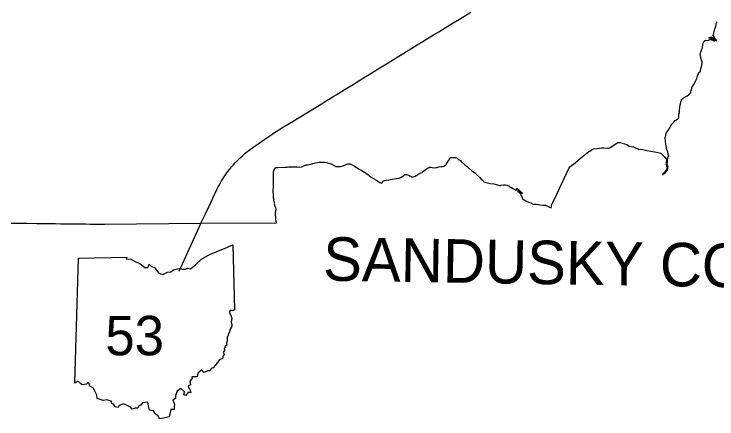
# Model space of a CAD drawing. Extents: x -82 to 873, y 0 to 440.
# Drawn here: x 319.9 to 400.6, y 101.2 to 147.6 of the extents above; entities that cross this region are included whole.
import ezdxf

# ---------------------------------------------------------------- set-up
doc = ezdxf.new("R2010")
doc.units = 0
for name, color, linetype in [('GM_X_Adjacent_County_Text', 7, 'Continuous'), ('GM_X_County', 7, 'Continuous'), ('GM_X_Interstate_Route', 7, 'Continuous'), ('PV_P_Text', 7, 'Continuous')]:
    doc.layers.add(name, color=color, linetype=linetype)

msp = doc.modelspace()

# ---------------------------------------------------------------- linework, layer by layer
at = {"layer": 'GM_X_County'}
msp.add_lwpolyline([(319.599, 123.64), (320.437, 123.634), (321.376, 123.619), (322.523, 123.608), (323.305, 123.602), (323.714, 123.595), (324.701, 123.586), (325.272, 123.578), (326.013, 123.57), (327.45, 123.55), (328.147, 123.544), (328.679, 123.539), (329.256, 123.531), (330.075, 123.525), (330.196, 123.525), (330.311, 123.522), (341.359, 123.643), (350.048, 123.686), (349.981, 124.068), (349.976, 124.298), (349.915, 124.639), (349.928, 124.886), (349.973, 125.03), (349.989, 125.249), (349.953, 125.379), (349.901, 125.562), (349.865, 125.676), (349.84, 125.756), (349.809, 125.765), (349.801, 125.795), (349.828, 125.859), (349.84, 125.945), (349.812, 126.003), (349.767, 126.059), (349.784, 126.084), (349.756, 126.278), (349.748, 126.339), (349.759, 126.377), (349.72, 126.413), (349.695, 126.483), (349.698, 126.621), (349.69, 126.818), (349.665, 127.403), (349.692, 127.863), (349.706, 128.237), (349.701, 128.775), (349.701, 129.121), (349.717, 129.515), (349.845, 129.942), (349.972, 130.025), (350.219, 130.045), (350.995, 130.081), (351.264, 130.078), (351.425, 130.106), (351.558, 130.097), (351.635, 130.075), (351.677, 130.086), (351.807, 130.086), (352.123, 130.1), (352.399, 130.09), (352.636, 130.084), (352.88, 130.106), (352.963, 130.109), (353.088, 130.189), (353.265, 130.258), (353.323, 130.303), (353.437, 130.283), (353.456, 130.322), (353.626, 130.336), (353.822, 130.389), (353.966, 130.405), (354.197, 130.475), (354.529, 130.56), (354.931, 130.658), (355.028, 130.638), (355.303, 130.633), (355.533, 130.622), (355.796, 130.602), (356.048, 130.544), (356.314, 130.439), (356.583, 130.295), (356.849, 130.159), (357.11, 130.128), (357.394, 130.146), (357.645, 130.217), (357.947, 130.331), (358.216, 130.439), (358.453, 130.443), (358.724, 130.343), (358.984, 130.182), (359.308, 129.991), (359.524, 129.837), (359.837, 129.68), (360.128, 129.5), (360.389, 129.349), (360.65, 129.158), (360.896, 128.931), (361.162, 128.776), (361.429, 128.624), (361.781, 128.394), (361.897, 128.302), (362.119, 128.222), (362.165, 128.316), (362.246, 128.435), (362.326, 128.501), (362.426, 128.532), (362.619, 128.578), (362.918, 128.627), (363.32, 128.686), (363.555, 128.722), (363.821, 128.766), (364.108, 128.808), (364.215, 128.829), (364.319, 128.889), (364.577, 129.089), (364.785, 129.21), (364.881, 129.237), (364.997, 129.217), (365.201, 129.14), (365.249, 129.102), (365.273, 129.055), (365.335, 129.057), (365.49, 128.982), (365.645, 128.932), (365.777, 128.948), (365.939, 129.022), (366.133, 129.162), (366.36, 129.318), (366.618, 129.412), (366.742, 129.464), (366.916, 129.607), (367.097, 129.754), (367.217, 129.834), (367.378, 129.947), (367.5, 129.987), (367.574, 130.023), (367.617, 130.017), (367.652, 130.048), (367.767, 130.051), (367.915, 130.019), (368.162, 129.996), (368.375, 130.044), (368.475, 130.043), (368.641, 130.094), (368.956, 130.128), (369.095, 130.136), (369.238, 130.169), (369.369, 130.243), (369.474, 130.315), (369.517, 130.389), (369.548, 130.441), (369.651, 130.592), (369.753, 130.776), (369.805, 130.83), (369.9, 131.015), (369.906, 131.057), (369.97, 131.13), (370.035, 131.166), (370.156, 131.173), (370.396, 131.184), (370.619, 131.183), (370.728, 131.149), (370.792, 131.101), (370.885, 130.995), (371.017, 130.909), (371.148, 130.836), (371.244, 130.735), (371.399, 130.603), (371.618, 130.388), (371.911, 130.161), (372.075, 129.997), (372.431, 129.698), (372.806, 129.426), (373.012, 129.218), (373.326, 128.911), (373.541, 128.697), (373.709, 128.569), (373.807, 128.419), (373.942, 128.345), (374.571, 128.2), (375.001, 128.138), (375.134, 128.104), (375.518, 128.014), (375.668, 127.97), (375.736, 127.968), (375.836, 127.993), (376.092, 128.021), (376.333, 128.034), (376.475, 128.016), (376.595, 127.97), (376.694, 127.918), (376.836, 127.802), (376.883, 127.778), (376.992, 127.717), (377.157, 127.632), (377.297, 127.55), (377.388, 127.491), (377.48, 127.431), (377.555, 127.419), (377.596, 127.446), (377.612, 127.477), (377.601, 127.579), (377.606, 127.598), (377.624, 127.604), (377.674, 127.598), (377.874, 127.442), (377.928, 127.384), (378.049, 127.273), (378.164, 127.182), (378.277, 127.089), (378.216, 127.03), (378.054, 127.143), (378.013, 127.176), (377.978, 127.211), (377.951, 127.263), (377.899, 127.309), (377.841, 127.347), (377.777, 127.38), (377.75, 127.37), (377.725, 127.342), (377.706, 127.29), (377.731, 127.268), (377.802, 127.235), (377.882, 127.176), (377.945, 127.114), (377.972, 127.08), (378.044, 127.03), (378.1, 126.923), (378.218, 126.597), (378.259, 126.427), (378.673, 126.209), (378.957, 126.065), (379.212, 125.964), (379.478, 125.824), (379.639, 125.803), (379.857, 125.827), (380.104, 125.791), (380.31, 125.74), (380.616, 125.694), (380.916, 125.703), (381.066, 125.636), (381.299, 125.527), (381.461, 125.43), (381.563, 125.406), (381.584, 125.561), (381.592, 125.686), (382.25, 127.053), (383.585, 129.908), (383.733, 130.143), (384.333, 130.577), (384.943, 131.108), (385.888, 131.873), (386.009, 131.914), (386.142, 132.006), (386.285, 132.084), (386.411, 132.159), (386.808, 132.198), (387.341, 132.278), (387.615, 132.287), (388.027, 132.266), (388.194, 132.254), (388.349, 132.321), (389.206, 132.9), (389.34, 132.91), (389.519, 132.881), (389.696, 132.828), (390.241, 132.661), (390.522, 132.494), (390.839, 132.416), (390.936, 132.435), (391.008, 132.394), (391.163, 132.329), (391.297, 132.247), (391.537, 132.154), (391.624, 132.113), (391.847, 132.121), (392.224, 132.041), (392.578, 131.983), (393.835, 131.75), (394.138, 131.661), (394.312, 131.525), (394.555, 131.239), (394.797, 130.997), (394.807, 130.876), (394.753, 130.522), (394.705, 130.45), (394.753, 130.382), (394.807, 130.207), (394.855, 129.989), (394.826, 129.863), (394.739, 129.696), (394.535, 129.452), (394.366, 129.289), (394.344, 129.241), (394.388, 129.214), (394.615, 129.398), (394.69, 129.427), (394.732, 129.515), (394.819, 129.648), (394.899, 129.774), (394.966, 129.922), (394.959, 130.125), (394.971, 130.19), (394.911, 130.222), (394.877, 130.362), (394.867, 130.568), (394.906, 130.67), (394.916, 130.936), (394.964, 131.077), (394.998, 131.28), (395.056, 131.293), (395.067, 131.368), (395.015, 131.411), (394.932, 131.779), (394.852, 132.077), (394.787, 132.286), (394.743, 132.496), (394.671, 133.012), (394.649, 133.501), (394.697, 133.567), (394.738, 133.688), (394.751, 133.952), (394.797, 134.063), (394.971, 134.281), (395.194, 134.587), (395.305, 134.831), (395.412, 135.011), (395.596, 135.183), (395.806, 135.415), (395.957, 135.517), (396.092, 135.619), (396.189, 135.711), (396.225, 135.781), (396.196, 136.144), (396.271, 136.331), (396.305, 136.478), (396.3, 136.612), (396.373, 137.229), (396.463, 137.658), (396.509, 137.774), (396.533, 137.823), (396.598, 137.862), (396.678, 137.932), (396.828, 138.053), (397.151, 138.252), (397.477, 138.503), (397.579, 138.639), (397.596, 138.768), (397.62, 138.857), (397.691, 139.114), (397.72, 139.233), (397.783, 139.313), (397.865, 139.443), (398.007, 139.665), (398.122, 139.941), (398.26, 140.247), (398.359, 140.572), (398.48, 140.824), (398.545, 140.923), (398.637, 140.994), (398.693, 141.059), (398.686, 141.166), (398.751, 141.408), (398.809, 141.589), (398.853, 141.749), (398.882, 142.016), (398.872, 142.151), (398.829, 142.343), (398.741, 142.655), (398.698, 142.919), (398.647, 143.05), (398.688, 143.207), (398.754, 143.28), (398.792, 143.404), (398.853, 143.597), (398.911, 143.781), (398.967, 144.152), (398.991, 144.29), (399.131, 144.532), (399.265, 144.666), (399.386, 144.607), (399.623, 144.663), (399.763, 144.733), (399.877, 144.726), (400.003, 144.695), (400.163, 144.634), (400.26, 144.578), (400.367, 144.571), (400.26, 144.658), (400.098, 144.741), (399.894, 144.826), (399.691, 144.864), (399.652, 144.915), (399.696, 144.959), (399.789, 144.986), (400.05, 144.986), (400.291, 144.796), (400.362, 144.763), (400.463, 144.631), (400.57, 144.588), (400.522, 144.654), (400.471, 144.68), (400.432, 144.731), (400.345, 144.876), (400.25, 145.036), (400.17, 145.167), (400.325, 145.942), (400.388, 146.039), (400.446, 146.269), (400.543, 146.645), (400.594, 146.737)], dxfattribs=at)
at = {"layer": 'GM_X_Interstate_Route'}
msp.add_line((341.359, 123.643), (338.818, 118.074), dxfattribs=at)
for points in [[(365.254, 143.529), (365.586, 143.733), (366.18, 144.099), (366.848, 144.508), (367.679, 145.013), (368.063, 145.252), (368.659, 145.616), (369.391, 146.064), (370.301, 146.622), (371.036, 147.074), (372.329, 147.867)], [(341.359, 123.643), (341.503, 123.938), (341.878, 124.714), (342.265, 125.53), (342.721, 126.495), (343.204, 127.493), (343.281, 127.651), (343.353, 127.797), (343.485, 128.05), (343.581, 128.219), (343.607, 128.266), (343.737, 128.485), (343.871, 128.712), (344.097, 129.055), (344.26, 129.291), (344.454, 129.556), (344.679, 129.848), (344.887, 130.102), (345.102, 130.35), (345.322, 130.593), (345.521, 130.8), (345.873, 131.145), (346.14, 131.385), (346.456, 131.657), (346.614, 131.784), (346.906, 132.011), (347.337, 132.325), (348.041, 132.822), (348.982, 133.482), (349.389, 133.759), (349.698, 133.959), (350.326, 134.35), (350.674, 134.568), (351.266, 134.928), (351.582, 135.121), (352.842, 135.894), (353.152, 136.084), (354.976, 137.202), (355.151, 137.311), (355.742, 137.672), (356.021, 137.846), (356.625, 138.219), (356.894, 138.385), (357.487, 138.747), (357.942, 139.027), (358.847, 139.577), (359.195, 139.795), (360.033, 140.313), (360.661, 140.703), (361.916, 141.479), (362.858, 142.063), (363.349, 142.362), (364.083, 142.814), (364.863, 143.289), (364.886, 143.303), (365.231, 143.516), (365.254, 143.529)]]:
    msp.add_lwpolyline(points, dxfattribs=at)
at = {"layer": 'PV_P_Text'}
msp.add_line((326.914, 105.263), (327.315, 119.626), dxfattribs=at)
msp.add_line((326.914, 105.263), (327.315, 119.626), dxfattribs=at)
for points in [[(327.315, 119.626), (332.887, 119.72), (332.8, 119.546), (333.326, 119.51), (333.885, 119.203), (334.357, 119.01), (334.935, 118.553), (335.281, 118.558), (335.427, 118.933), (335.692, 118.644), (336.006, 118.592), (336.549, 117.905), (336.998, 117.756), (337.535, 117.992), (337.936, 118.03), (338.23, 118.263), (338.994, 118.462), (339.208, 118.343), (339.612, 118.367), (339.816, 118.455), (340.169, 118.377), (340.791, 118.899), (341.431, 119.515), (342.415, 120.096), (343.885, 120.646), (345.047, 121.139), (345.216, 113.685)], [(327.315, 119.626), (332.887, 119.72), (332.8, 119.546), (333.326, 119.51), (333.885, 119.203), (334.357, 119.01), (334.935, 118.553), (335.281, 118.558), (335.427, 118.933), (335.692, 118.644), (336.006, 118.592), (336.549, 117.905), (336.998, 117.756), (337.535, 117.992), (337.936, 118.03), (338.23, 118.263), (338.994, 118.462), (339.208, 118.343), (339.612, 118.367), (339.816, 118.455), (340.169, 118.377), (340.791, 118.899), (341.431, 119.515), (342.415, 120.096), (343.885, 120.646), (345.047, 121.139), (345.216, 113.685)], [(345.216, 113.685), (345.044, 113.581), (344.777, 113.63), (344.598, 113.421), (344.82, 113.072), (344.925, 112.704), (344.832, 112.298), (344.924, 111.963), (344.861, 111.682), (344.693, 111.403), (344.635, 111.137), (344.493, 110.857), (344.505, 110.7), (344.369, 110.576), (344.393, 110.109), (344.325, 109.851), (344.348, 109.628), (344.128, 109.57), (344.178, 109.386), (344.038, 109.244), (344.068, 108.999), (343.909, 108.843), (344.063, 108.53), (343.939, 108.431), (343.836, 108.051), (343.553, 107.973), (342.987, 107.278), (342.787, 107.015), (342.562, 106.949), (342.438, 106.679), (342.162, 106.678), (341.743, 106.491), (341.472, 106.813), (340.998, 106.425), (340.944, 105.978), (340.344, 105.992), (340.368, 105.765), (340.234, 105.699), (340.112, 105.473), (340.183, 105.069), (339.902, 104.967), (339.936, 104.733), (340.116, 104.589), (340.196, 104.142), (339.898, 104.233), (339.653, 103.856), (339.402, 103.944), (339.484, 104.264), (339.06, 104.648), (338.658, 104.34), (338.449, 103.849), (338.446, 103.518), (338.147, 103.318), (338.339, 102.851), (338.304, 102.529), (338.31, 102.224), (337.936, 102.235), (337.709, 101.41)], [(345.216, 113.685), (345.044, 113.581), (344.777, 113.63), (344.598, 113.421), (344.82, 113.072), (344.925, 112.704), (344.832, 112.298), (344.924, 111.963), (344.861, 111.682), (344.693, 111.403), (344.635, 111.137), (344.493, 110.857), (344.505, 110.7), (344.369, 110.576), (344.393, 110.109), (344.325, 109.851), (344.348, 109.628), (344.128, 109.57), (344.178, 109.386), (344.038, 109.244), (344.068, 108.999), (343.909, 108.843), (344.063, 108.53), (343.939, 108.431), (343.836, 108.051), (343.553, 107.973), (342.987, 107.278), (342.787, 107.015), (342.562, 106.949), (342.438, 106.679), (342.162, 106.678), (341.743, 106.491), (341.472, 106.813), (340.998, 106.425), (340.944, 105.978), (340.344, 105.992), (340.368, 105.765), (340.234, 105.699), (340.112, 105.473), (340.183, 105.069), (339.902, 104.967), (339.936, 104.733), (340.116, 104.589), (340.196, 104.142), (339.898, 104.233), (339.653, 103.856), (339.402, 103.944), (339.484, 104.264), (339.06, 104.648), (338.658, 104.34), (338.449, 103.849), (338.446, 103.518), (338.147, 103.318), (338.339, 102.851), (338.304, 102.529), (338.31, 102.224), (337.936, 102.235), (337.709, 101.41)], [(337.709, 101.41), (337.059, 101.252), (336.608, 101.158), (336.448, 101.533), (336.125, 101.73), (335.915, 102.107), (335.452, 102.158), (335.342, 102.676), (335.29, 103.097), (334.656, 102.993), (334.482, 102.736), (334.258, 102.667), (334.127, 102.408), (333.82, 102.386), (333.492, 102.264), (333.277, 102.518), (332.738, 102.773), (332.496, 102.904), (331.989, 102.7), (331.881, 102.458), (331.478, 102.565), (331.384, 102.834), (331.14, 102.915), (331.086, 103.201), (330.564, 103.354), (330.165, 103.293), (329.462, 103.523), (329.419, 103.9), (329.179, 104.358), (329.054, 104.677), (328.61, 104.92), (328.519, 105.299), (328.377, 105.287), (328.247, 105.134), (327.753, 105.063), (327.556, 105.218), (327.279, 105.482), (326.914, 105.263)], [(337.709, 101.41), (337.059, 101.252), (336.608, 101.158), (336.448, 101.533), (336.125, 101.73), (335.915, 102.107), (335.452, 102.158), (335.342, 102.676), (335.29, 103.097), (334.656, 102.993), (334.482, 102.736), (334.258, 102.667), (334.127, 102.408), (333.82, 102.386), (333.492, 102.264), (333.277, 102.518), (332.738, 102.773), (332.496, 102.904), (331.989, 102.7), (331.881, 102.458), (331.478, 102.565), (331.384, 102.834), (331.14, 102.915), (331.086, 103.201), (330.564, 103.354), (330.165, 103.293), (329.462, 103.523), (329.419, 103.9), (329.179, 104.358), (329.054, 104.677), (328.61, 104.92), (328.519, 105.299), (328.377, 105.287), (328.247, 105.134), (327.753, 105.063), (327.556, 105.218), (327.279, 105.482), (326.914, 105.263)]]:
    msp.add_lwpolyline(points, dxfattribs=at)

# ---------------------------------------------------------------- texts
at = {"layer": 'GM_X_Adjacent_County_Text'}
msp.add_text('SANDUSKY COUNTY', height=5, rotation=359.06378, dxfattribs=at).set_placement((355.36, 117.047))
at = {"layer": 'PV_P_Text'}
msp.add_text('53', height=4.5281, rotation=0.005, dxfattribs=at).set_placement((330.402, 108.467))

doc.saveas('drawing.dxf')
